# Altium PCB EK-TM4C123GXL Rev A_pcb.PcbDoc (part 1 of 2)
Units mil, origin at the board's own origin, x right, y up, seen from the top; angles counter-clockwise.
Board outline 2000 x 2600 mil, 2 copper layers (Top, Bottom), stack 12.7 mil thick; 107 components, 90 nets, 409 pads, 197 vias.
Unrouted connection lines stored in the file: 66.
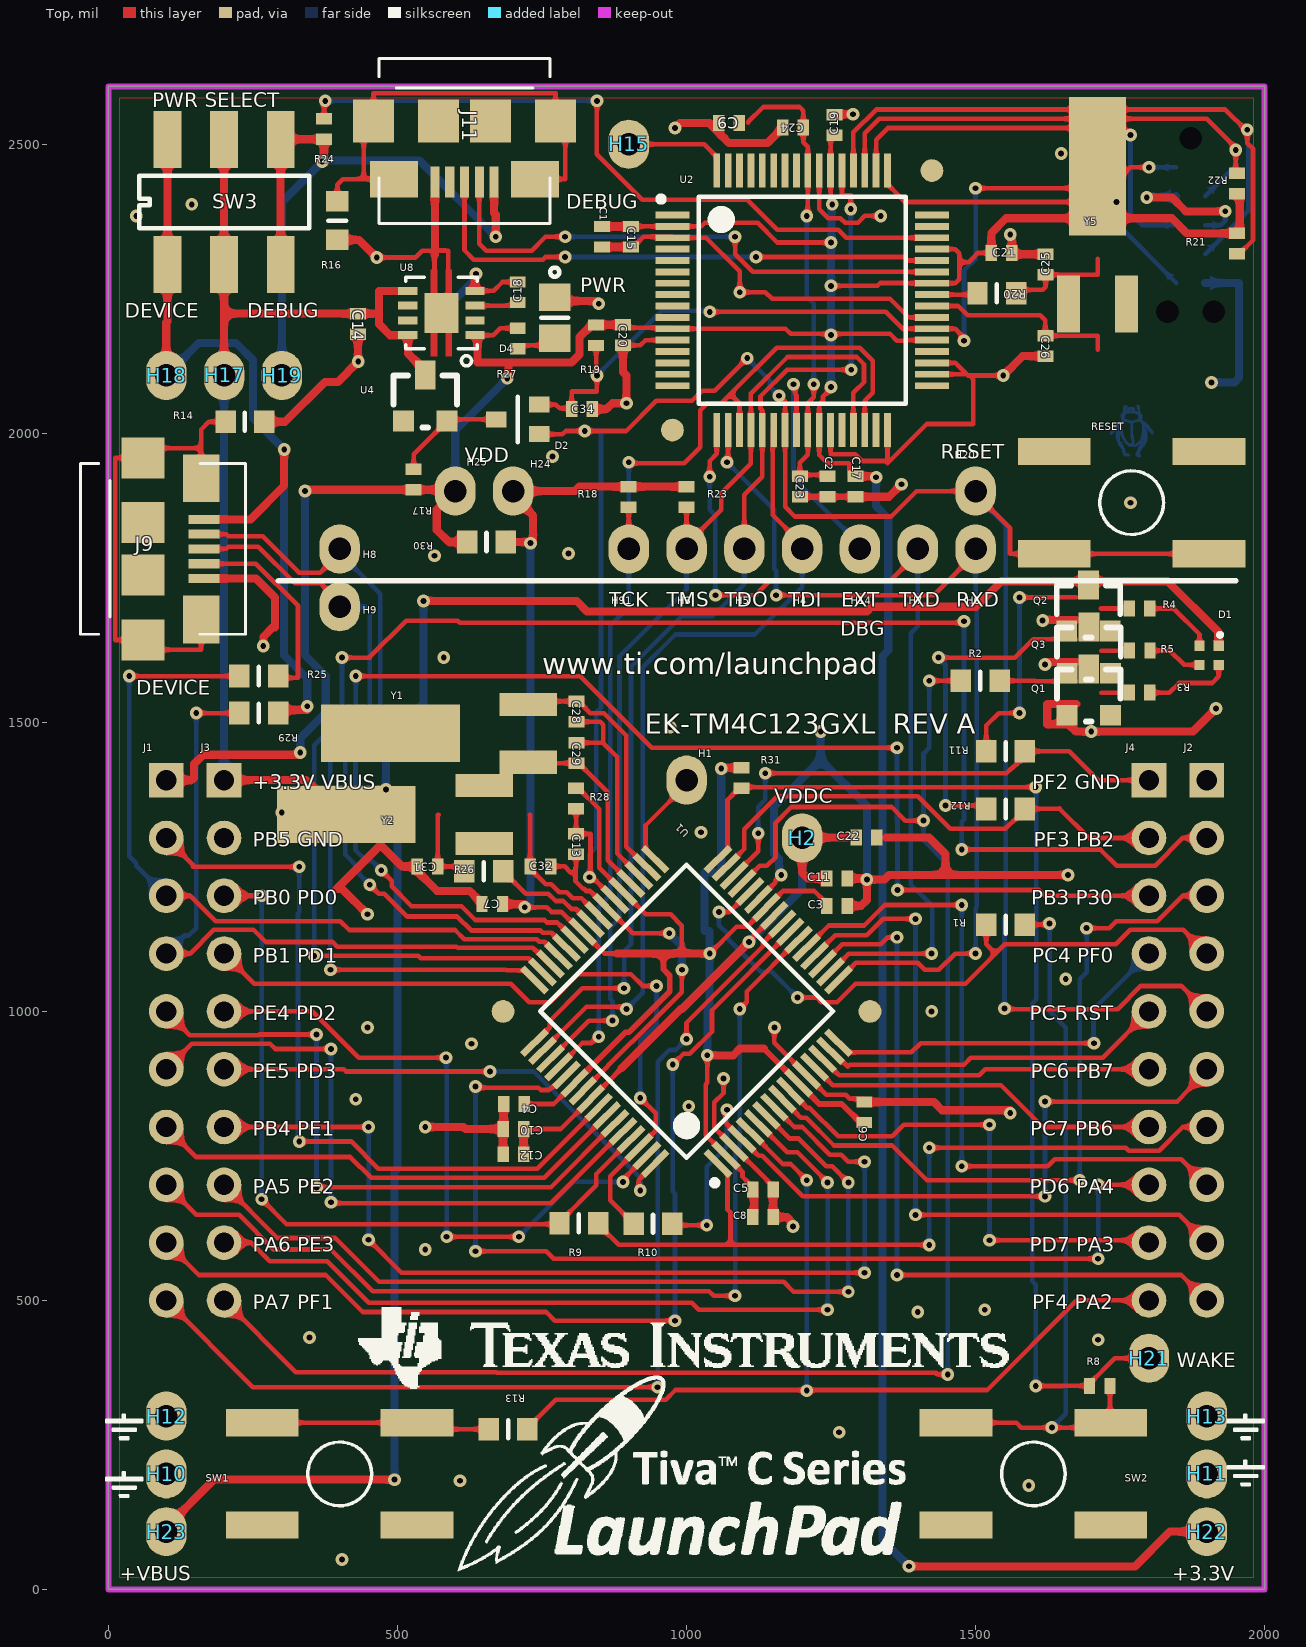
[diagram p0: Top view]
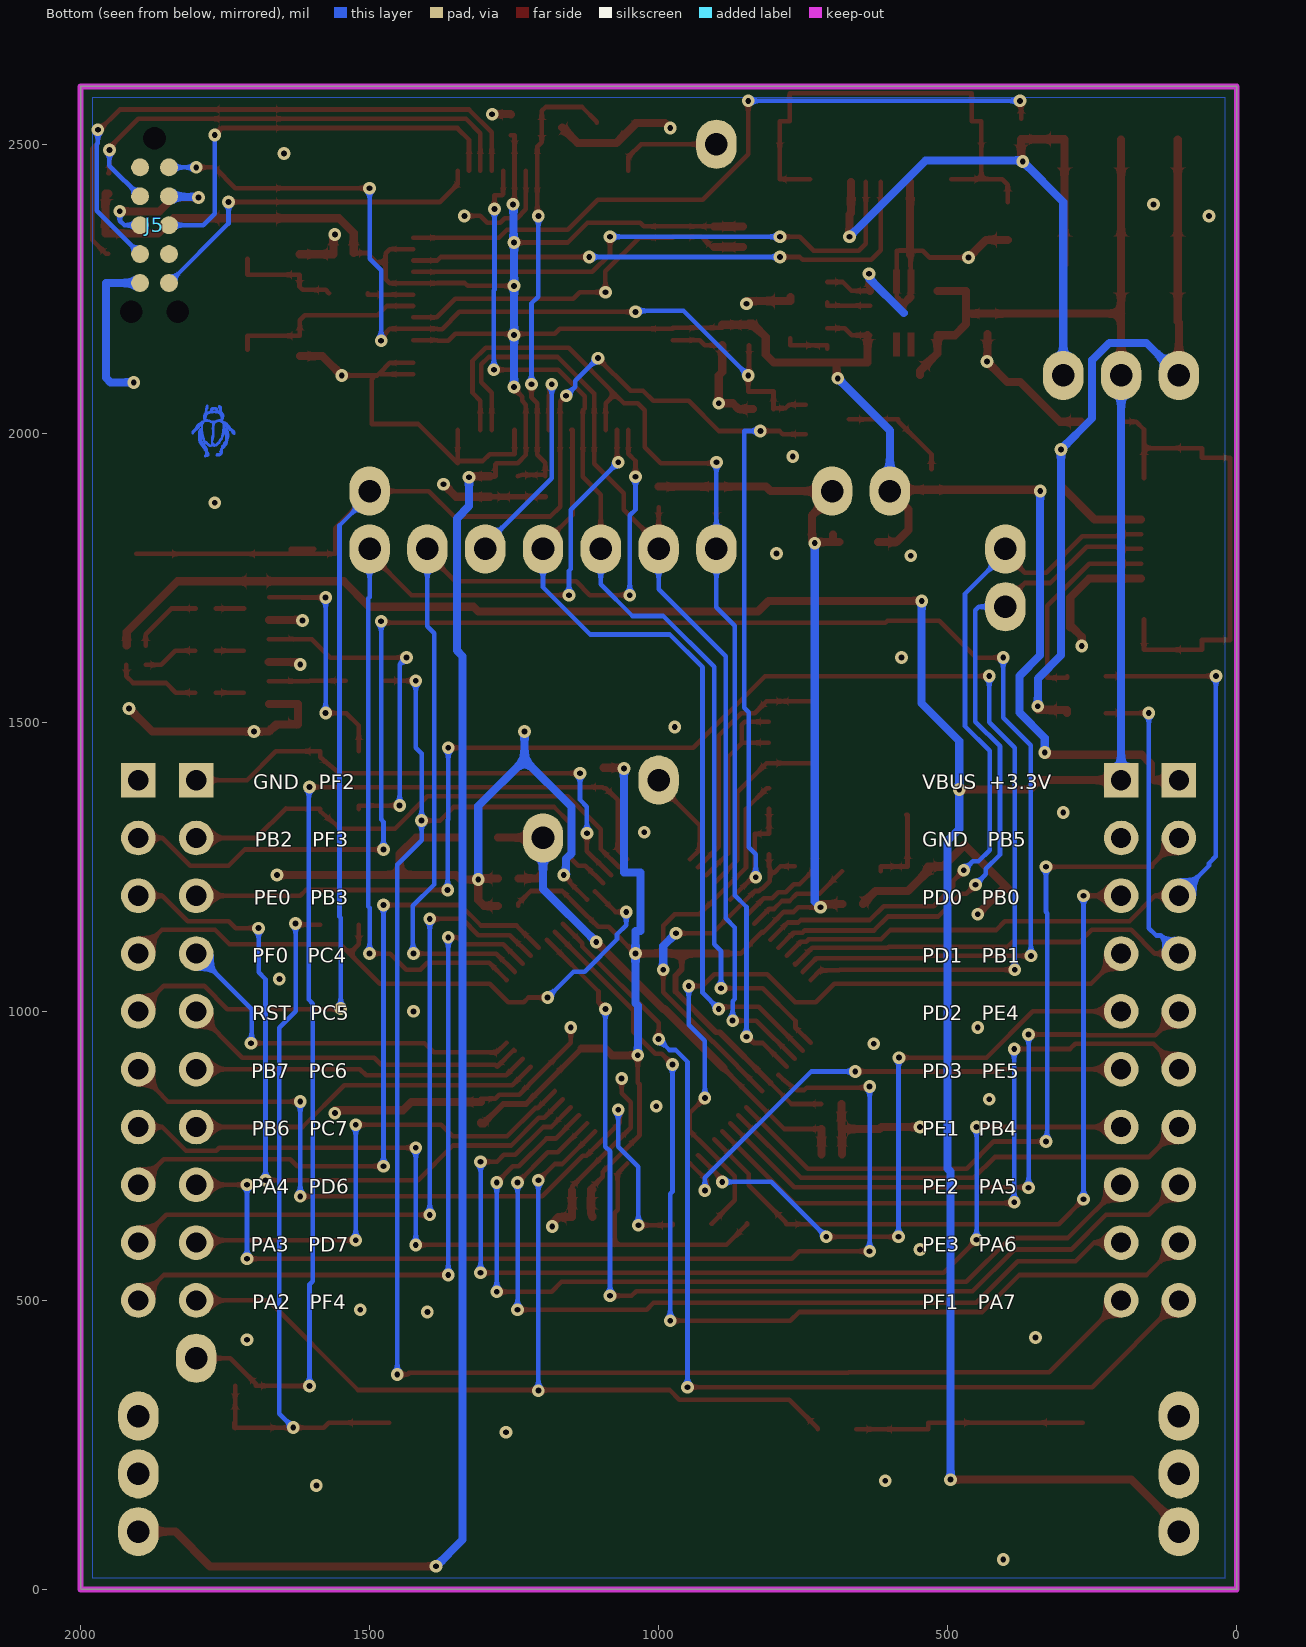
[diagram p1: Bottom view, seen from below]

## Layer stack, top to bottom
Solder Mask Top: solder mask 0.4, Solder Resist, Dk 3.5
Top: signal copper 1.35
Dielectric 1: dielectric 10, FR-4, Dk 4.3
Bottom: signal copper 1.35
Solder Mask Bottom: solder mask 0.4, Solder Resist, Dk 3.5

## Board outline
0,0 0,2600 2000,2600 2000,0

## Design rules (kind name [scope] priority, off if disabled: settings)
Clearance "Clearance - Default - DEFAULT - Via" [IsVia vs IsVia] p1: gap=7
Clearance "Clearance - Default - DEFAULT- SMD" [IsVia vs IsSMTPin] p2: gap=7
Clearance "Clearance - Default - DEFAULT - Net" [All] p3: gap=7 except(10: Text-Text)
ComponentClearance "ComponentClearance - Default - DEFAULT" [All] p1: gap=10 collisioncheckmode=3 verticalgap=10 showdistances=FALSE
DiffPairsRouting "DiffPairsRouting - DiffPair - USB_D" [InDifferentialPair('USB_D')] p1: maxlimit=10 minlimit=10 mostfreqgap=10 toplayer_minwidth=8 toplayer_maxwidth=8 toplayer_prefwidth=8 bottomlayer_minwidth=8 bottomlayer_maxwidth=8 bottomlayer_prefwidth=8 maxuncoupledlength=500
FanoutControl Fanout_SOIC [IsSOIC] p1: bgadir=Out bgaviamode=Centered fanoutstyle=Auto fanoutdirection=Alternating viagrid=1 // Fanout_SOIC (Default Rule)
FanoutControl Fanout_Small [(CompPinCount < 5)] p2: bgadir=Out bgaviamode=Centered fanoutstyle=Auto fanoutdirection=OutThenIn viagrid=1 // Fanout_Small (Default Rule)
FanoutControl Fanout_LCC [IsLCC] p3: bgadir=Out bgaviamode=Centered fanoutstyle=Auto fanoutdirection=Alternating viagrid=1 // Fanout_LCC (Default Rule)
FanoutControl Fanout_BGA [IsBGA] p4: bgadir=Out bgaviamode=Centered fanoutstyle=Auto fanoutdirection=Alternating viagrid=1 // Fanout_BGA (Default Rule)
HoleToHoleClearance "HoleToHoleClearance - Default - DEFAULT" [All] p1: gap=10 allowstackedmicrovias=TRUE
Length "Length - DiffPair - USB_D" [InDifferentialPair('USB_D')] p1: maxlimit=50000 minlimit=0
Length "Default Length" [All] p2: maxlimit=50000 minlimit=0
MatchedLengths "MatchedLengths - DiffPair - USB_D" [InDifferentialPair('USB_D')] p1: tolerance=200 checknetsindiffpair=TRUE checkdiffpairvsdiffpair=FALSE checkxsignals=FALSE checkothers=FALSE
MaxMinImpedance "Default Impedance" [All] p1: minimum=50,00 maximum=150,0
ParallelSegment "Default Parallel Segment Same Layer" [All] p1: limit=1000 gap=200
ParallelSegment "Default Parallel Segment Adjasent" [All] p2: limit=1000 gap=200
PlaneConnect "Default PlaneConnect" [All] p1: planeconnectstyle=Relief reliefexpansion=20 reliefentries=0 reliefconductorwidth=10 reliefairgap=10
PolygonConnect "PolygonConnect - Default SMT" [IsSMTPin] p1: connectstyle=Relief reliefconductorwidth=10 reliefentries=4 polygonreliefangle="45 Angle" airgapwidth=10
PolygonConnect "PolygonConnect - Default Pad" [All] p2: connectstyle=Relief reliefconductorwidth=10 reliefentries=4 polygonreliefangle="45 Angle" airgapwidth=10
RoutingLayers "RoutingLayers - Default - DEFAULT" [All] p1: top layer_v5=TRUE bottom layer_v5=TRUE
RoutingPriority "RoutingPriority - Default - DEFAULT" [All] p1: routingpriority=3
RoutingTopology "Default Routing Topology" [All] p1: topology=Shortest
RoutingVias "RoutingVias - Default - DEFAULT" [All] p1: holewidth=10 width=22 viastyle="Through Hole" minholewidth=10 minwidth=22 maxholewidth=10 maxwidth=22
SMDToCorner "SMDToCorner - Default - DEFAULT" [All] p1: distance=70000
SolderMaskExpansion "SolderMaskExpansion from CAM settings" [All] p1: expansion=5
Width "Width - NetClass - CLASS_0" [InNetClass('CLASS_0')] p1: maxlimit=14 minlimit=8 preferedwidth=14
Width "Default Width" [All] p2: maxlimit=8 minlimit=8 preferedwidth=8
19 further rules are at their usual default settings.

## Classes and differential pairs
net class CLASS_0: +3.3V +ICDI_VBUS +MCU_PWR +MCU_VDDC +USB_VBUS +VBUS GND
differential pair USB_D: +USB_DP -USB_DM

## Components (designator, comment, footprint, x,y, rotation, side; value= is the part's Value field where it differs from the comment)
C1 "CAPC0402N" CAPC0402N 853.75,2340.02 r270 top
C2 "CAPC0402N" CAPC0402N 1244,1908 r270 top
C3 "CAPC0402N" CAPC0402N 1260.48,1182.63 r0 top
C4 "CAPC0402N" CAPC0402N 701.43,839.77 r180 top
C5 "CAPC0402N" CAPC0402N 1132,692 r0 top
C6 "CAPC0402N" CAPC0402N 1307.38,825.52 r90 top
C7 "CAPC0402N" CAPC0402N 663.91,1185.82 r180 top
C8 "CAPC0402N" CAPC0402N 1132,644 r0 top
C9 "CAPC0402N" CAPC0402N 1073.59,2537.02 r180 top
C10 "CAPC0402N" CAPC0402N 700.95,796.54 r180 top
C11 "CAPC0402N" CAPC0402N 1260,1230 r0 top
C12 "CAPC0402N" CAPC0402N 700.48,752.84 r180 top
C13 "CAPC0402N" CAPC0402N 808.97,1289.39 r270 top
C14 "CAPC0402N" CAPC0402N 431.44,2189.32 r270 top
C15 "CAPC0402N" CAPC0402N 904,2340 r270 top
C17 "CAPC0402N" CAPC0402N 1292,1908 r270 top
C18 "CAPC0402N" CAPC0402N 708,2244 r90 top
C19 "CAPC0402N" CAPC0402N 1255.65,2533.39 r90 top
C20 "CAPC0402N" CAPC0402N 890,2170 r270 top
C21 "CAPC0402N" CAPC0402N 1545.01,2311.96 r0 top
C22 "CAPC0402N" CAPC0402N 1311.41,1300.63 r0 top
C23 "CAPC0402N" CAPC0402N 1196,1908 r270 top
C24 "CAPC0402N" CAPC0402N 1184.34,2528.94 r180 top
C25 "CAPC0402N" CAPC0402N 1621.26,2291.93 r90 top
C26 "CAPC0402N" CAPC0402N 1620.61,2151.07 r270 top
C28 "CAPC0402N" CAPC0402N 809.45,1518.67 r270 top
C29 "CAPC0402N" CAPC0402N 809.45,1447.07 r270 top
C31 "CAPC0402N" CAPC0402N 551.81,1250.59 r180 top
C32 "CAPC0402N" CAPC0402N 747.1,1250.85 r0 top
C34 "CAPC0402N" CAPC0402N 819.03,2041.82 r0 top
D1 "0404_QUAD" 0404_QUAD 1904,1616 r270 top
D2 "SC70-3" SC70-3 708,2024 r180 top
D4 "DIOC0805N" DIOC0805N 772,2200 r270 top
H1 "PAD70H39" PAD70H39 1000,1400 r0 top
H2 "PAD70H39" PAD70H39 1200,1300 r0 top
H3 "PAD70H39" PAD70H39 1000,1800 r0 top
H4 "PAD70H39" PAD70H39 1200,1800 r0 top
H5 "PAD70H39" PAD70H39 1100,1800 r0 top
H6 "PAD70H39" PAD70H39 1500,1800 r0 top
H7 "PAD70H39" PAD70H39 1400,1800 r0 top
H8 "PAD70H39" PAD70H39 400,1800 r0 top
H9 "PAD70H39" PAD70H39 400,1700 r0 top
H10 "PAD70H39" PAD70H39 100,200 r0 top
H11 "PAD70H39" PAD70H39 1900,200 r0 top
H12 "PAD70H39" PAD70H39 100,300 r0 top
H13 "PAD70H39" PAD70H39 1900,300 r0 top
H14 "PAD70H39" PAD70H39 1300,1800 r0 top
H15 "PAD70H39" PAD70H39 900,2500 r0 top
H17 "PAD70H39" PAD70H39 200,2100 r0 top
H18 "PAD70H39" PAD70H39 100,2100 r0 top
H19 "PAD70H39" PAD70H39 300,2100 r0 top
H20 "PAD70H39" PAD70H39 1500,1900 r0 top
H21 "PAD70H39" PAD70H39 1800,400 r0 top
H22 "PAD70H39" PAD70H39 1900,100 r0 top
H23 "PAD70H39" PAD70H39 100,100 r0 top
H24 "PAD70H39" PAD70H39 700,1900 r0 top
H25 "PAD70H39" PAD70H39 600,1900 r0 top
H91 "PAD70H39" PAD70H39 900,1800 r0 top
J1 "TSW-110-100" TSW-110-100 100,1400 r0 top
J2 "TSW-110-100" TSW-110-100 1900,1400 r0 top
J3 "TSW-110-100" TSW-110-100 200,1400 r0 top
J4 "TSW-110-100" TSW-110-100 1800,1400 r0 top
J5 "TC2050-IDC-NL" TC2050-IDC-NL 1872,2360 r270 bottom
J9 "CON-USB-MICRO-S" CON-USB-MICRO-S 60,1800 r0 top
J11 "CON-USB-MICRO-S" CON-USB-MICRO-S 616,2540 r270 top
Q1 "SOT23" SOT23 1695.78,1551.33 r0 top
Q2 "SOT23" SOT23 1695.38,1696.82 r0 top
Q3 "SOT23" SOT23 1696,1624 r0 top
R1 "RESC0603N" RESC0603N 1552,1150 r0 top
R2 "RESC0603N" RESC0603N 1508,1572 r0 top
R3 "RESC0402N" RESC0402N 1783.78,1551.33 r0 top
R4 "RESC0402N" RESC0402N 1783.38,1696.82 r0 top
R5 "RESC0402N" RESC0402N 1784,1624 r0 top
R8 "RESC0402N" RESC0402N 1714.79,352.28 r0 top
R9 "RESC0603N" RESC0603N 813.73,633.34 r0 top
R10 "RESC0603N" RESC0603N 942.02,632.6 r0 top
R11 "RESC0603N" RESC0603N 1552,1450 r180 top
R12 "RESC0603N" RESC0603N 1552,1350 r180 top
R13 "RESC0603N" RESC0603N 691.28,277.06 r180 top
R14 "RESC0603N" RESC0603N 236,2020 r0 top
R16 "RESC0603N" RESC0603N 396,2368 r270 top
R17 "RESC0402N" RESC0402N 528,1920 r90 top
R18 "RESC0402N" RESC0402N 900,1890 r270 top
R19 "RESC0402N" RESC0402N 843.63,2169.67 r270 top
R20 "RESC0603N" RESC0603N 1536.82,2242.17 r180 top
R21 "RESC0402N" RESC0402N 1952,2328 r270 top
R22 "RESC0402N" RESC0402N 1952,2432 r90 top
R23 "RESC0402N" RESC0402N 1000,1890 r270 top
R24 "RESC0402N" RESC0402N 372.94,2526.34 r270 top
R25 "RESC0603N" RESC0603N 260,1580 r0 top
R26 "RESC0603N" RESC0603N 649.32,1242.46 r0 top
R27 "RESC0402N" RESC0402N 708,2164 r270 top
R28 "RESC0402N" RESC0402N 808.97,1368.29 r270 top
R29 "RESC0603N" RESC0603N 260,1516 r180 top
R30 "RESC0603N" RESC0603N 654,1812 r180 top
R31 "RESC0402N" RESC0402N 1095.16,1403.7 r270 top
RESET "SW-EVQQ2" SW-EVQQ2 1770,1880 r0 top
SW1 "SW-EVQQ2" SW-EVQQ2 400,200 r0 top
SW2 "SW-EVQQ2" SW-EVQQ2 1600,200 r0 top
SW3 "SW_JS202011SCQN" SW_JS202011SCQN 200,2400 r90 top
U1 "QFP50P1200X1200X160-64N" QFP50P1200X1200X160-64N 1000,1000 r135 top
U2 "QFP50P1200X1200X160-64N" QFP50P1200X1200X160-64N 1200,2230 r0 top
U4 "SOT23" SOT23 548,2060 r0 top
U8 "TI-DRB-SON8" TI-DRB-SON8 576,2208 r90 top
Y1 "XTAL-AB26TRA" XTAL-AB26TRA 726.3,1480.94 r0 top
Y2 "XTAL-AB26TRA" XTAL-AB26TRA 650.08,1340.44 r0 top
Y5 "XTAL-AB26TRA" XTAL-AB26TRA 1711.07,2223.44 r270 top

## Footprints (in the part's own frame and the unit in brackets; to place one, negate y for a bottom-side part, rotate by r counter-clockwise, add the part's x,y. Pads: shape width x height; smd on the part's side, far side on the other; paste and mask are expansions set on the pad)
0404_QUAD [mm]
  rrect0% 0.45x0.45 smd: 1(-0.423,0.423) 2(0.423,0.423) 3(0.423,-0.423) 4(-0.423,-0.423)
  silkscreen extent -0.98,0.41 -0.82,0.56
CAPC0402N [mm]
  rect 0.5x0.7 smd: 1(-0.45,0) 2(0.45,0)
CON-USB-MICRO-S [mm]
  rect 1.35x0.4 smd: 1(2.675,1.3) 2(2.675,0.65) 3(2.675,0) 4(2.675,-0.65) 5(2.675,-1.3)
  rect 1.6x2.1 smd: 6(2.55,3.1) 7(2.55,-3.1)
  rect 1.9x1.8 smd: 8(0,4) 9(0,-4) 10(0,1.15) 11(0,-1.15)
  silkscreen extent -2.75,-3.75 4.5,3.75
DIOC0805N [mm]
  rect 1.2x1.4 smd: 1(-0.9,0) 2(0.9,0)
  silkscreen extent -2.2,-0.6 0,0.6
PAD70H39 [mil]
  oval 70x85 / inner round 70 / far side oval 70x85 hole 39: 1(0,0)
QFP50P1200X1200X160-64N [mm]
  rect 1.5x0.3 smd: 1(-5.7,3.75) 2(-5.7,3.25) 3(-5.7,2.75) 4(-5.7,2.25) 5(-5.7,1.75) 6(-5.7,1.25) 7(-5.7,0.75) 8(-5.7,0.25) 9(-5.7,-0.25) 10(-5.7,-0.75) 11(-5.7,-1.25) 12(-5.7,-1.75) 13(-5.7,-2.25) 14(-5.7,-2.75) 15(-5.7,-3.25) 16(-5.7,-3.75) 33(5.7,-3.75) 34(5.7,-3.25) 35(5.7,-2.75) 36(5.7,-2.25) 37(5.7,-1.75) 38(5.7,-1.25) 39(5.7,-0.75) 40(5.7,-0.25) 41(5.7,0.25) 42(5.7,0.75) 43(5.7,1.25) 44(5.7,1.75) 45(5.7,2.25) 46(5.7,2.75) 47(5.7,3.25) 48(5.7,3.75)
  rect 0.3x1.5 smd: 17(-3.75,-5.7) 18(-3.25,-5.7) 19(-2.75,-5.7) 20(-2.25,-5.7) 21(-1.75,-5.7) 22(-1.25,-5.7) 23(-0.75,-5.7) 24(-0.25,-5.7) 25(0.25,-5.7) 26(0.75,-5.7) 27(1.25,-5.7) 28(1.75,-5.7) 29(2.25,-5.7) 30(2.75,-5.7) 31(3.25,-5.7) 32(3.75,-5.7) 49(3.75,5.7) 50(3.25,5.7) 51(2.75,5.7) 52(2.25,5.7) 53(1.75,5.7) 54(1.25,5.7) 55(0.75,5.7) 56(0.25,5.7) 57(-0.25,5.7) 58(-0.75,5.7) 59(-1.25,5.7) 60(-1.75,5.7) 61(-2.25,5.7) 62(-2.75,5.7) 63(-3.25,5.7) 64(-3.75,5.7)
  round 1 smd mask+0.5: 65(-5.7,-5.7) 66(5.7,5.7)
  Top pour cut-out: 6.7,5.7 6.624,6.083 6.407,6.407 6.083,6.624 5.7,6.7 5.7,6.7 5.317,6.624 4.993,6.407 4.776,6.083 4.7,5.7 4.7,5.7 4.776,5.317 4.993,4.993 5.317,4.776 5.7,4.7 5.7,4.7 6.083,4.776 6.407,4.993 6.624,5.317 6.7,5.7
  Top pour cut-out: -4.7,-5.7 -4.776,-5.317 -4.993,-4.993 -5.317,-4.776 -5.7,-4.7 -5.7,-4.7 -6.083,-4.776 -6.407,-4.993 -6.624,-5.317 -6.7,-5.7 -6.7,-5.7 -6.624,-6.083 -6.407,-6.407 -6.083,-6.624 -5.7,-6.7 -5.7,-6.7 -5.317,-6.624 -4.993,-6.407 -4.776,-6.083 -4.7,-5.7
  silkscreen extent -6.32,-4.55 4.55,4.57
RESC0402N [mm]
  rect 0.5x0.7 smd: 1(-0.45,0) 2(0.45,0)
RESC0603N [mm]
  rect 0.9x1 smd: 1(-0.85,0) 2(0.85,0)
  silkscreen extent 0,-0.4 0,0.4
SC70-3 [mm]
  rect 0.9x0.7 smd: 1(-0.95,0.65) 2(-0.95,-0.65) 3(0.95,0)
  silkscreen extent 0,-1 0,1
SOT23 [mil]
  rect 36x36 smd: 1(-37.5,-39) 2(37.5,-39)
  rect 36x50 smd: 3(0,41)
  silkscreen extent -55,-50 55,40
SW-EVQQ2 [mm]
  rect 3.2x1.2 smd: 1(-3.4,2.25) 2(-3.4,-2.25) 3(3.4,2.25) 4(3.4,-2.25)
  silkscreen extent -1.4,-1.4 1.4,1.4
SW_JS202011SCQN [mil]
  rect 98.5x48 smd: 1(-108.25,98) 2(-108.25,0) 3(-108.25,-98) 4(108.25,-98) 5(108.25,0) 6(108.25,98)
  silkscreen extent -45,-147 45,147
TC2050-IDC-NL [mil]
  round 31 smd paste-15.5: 1(-100,-25) 2(-50,-25) 3(0,-25) 4(50,-25) 5(100,-25) 6(100,25) 7(50,25) 8(0,25) 9(-50,25) 10(-100,25)
  round 0 hole 39 unplated: 11(-150,0) 12(150,-40) 13(150,40)
  Top pour cut-out: -100,-14 100,-14 100,13 -100,13 -100,-14
TI-DRB-SON8 [mm]
  rect 0.35x0.85 smd: 1(-0.975,-1.475) 2(-0.325,-1.475) 3(0.325,-1.475) 4(0.975,-1.475) 5(0.975,1.475) 6(0.325,1.475) 7(-0.325,1.475) 8(-0.975,1.475)
  rrect1% 1.75x1.5 smd paste-0.1: 9(0,0)
  round 0 all layers, no hole: 10(0,0) 11(0,0) 12(0,0) 13(0,0)
  Top region: 1.9,-0.185 0.875,-0.185 0.875,-0.465 1.9,-0.465 1.9,-0.185
  Top region: 1.9,0.465 0.875,0.465 0.875,0.185 1.9,0.185 1.9,0.465
  Top region: -0.875,-0.185 -1.9,-0.185 -1.9,-0.465 -0.875,-0.465 -0.875,-0.185
  Top region: -0.875,0.465 -1.9,0.465 -1.9,0.185 -0.875,0.185 -0.875,0.465
  silkscreen extent -2.32,-1.58 1.58,1.58
TSW-110-100 [mil]
  rect 60x60 / inner round 60 / far side rect 60x60 hole 35: 1(0,0)
  round 60 hole 35: 2(0,-100) 3(0,-200) 4(0,-300) 5(0,-400) 6(0,-500) 7(0,-600) 8(0,-700) 9(0,-800) 10(0,-900)
XTAL-AB26TRA [mil]
  rect 99x40 smd: 1(0,-50) 2(0,50)
  rect 240x99 smd: 3(-238.5,0)

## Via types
v1: diameter 22, hole 10, Top to Bottom, 197 vias

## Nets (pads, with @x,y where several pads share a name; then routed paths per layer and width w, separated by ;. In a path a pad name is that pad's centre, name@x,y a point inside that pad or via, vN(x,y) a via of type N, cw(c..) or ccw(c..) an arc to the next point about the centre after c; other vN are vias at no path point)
$$$7473: R4.1 | length 48.6
  Top w8: 1717.04,1696.82 1734.75,1696.82 R4.1@1765.66,1696.82
$$$7634: C29.2 U1.36 Y1.1 | length 334.2
  Top w8: Y1.1@726.3,1430.94 726.3,1429.35 813.39,1429.35 864,1378.74 864,1261.27 U1.36@903.96,1221.32
$$$7643: C28.2 C29.1 U1.35 | length 381.9
  Top w8: C29.1@809.45,1464.79 855.21,1464.79 856,1464 ; C28.2@809.45,1500.95 851.05,1500.95 856,1496 856,1464 ; U1.35@917.88,1235.24 880,1273.11 880,1440 856,1464
$$$7651: C28.1 U1.34 Y1.2 | length 442.5
  Top w8: Y1.2@726.3,1530.94 726.3,1536.39 C28.1@809.45,1536.39 813.39,1536.39 833.77,1516 857.21,1516 896,1477.21 896,1284.95 U1.34@931.79,1249.16
$$$9519: D4.2 R27.2 | length 82.3
  Top w8: R27.2@708,2146.28 708,2152.13 772,2152.13 D4.2@772,2164.57
$$$9631: C2.1 C9.1 C23.1 C24.1 U2.25 U2.56 | length 810.8
  Top w8: 1107.05,2537.02 1107.05,2538.98 1132.54,2564.48 1195.52,2564.48 1202.06,2557.94 1202.06,2503.78 1209.84,2496 U2.56@1209.84,2454.41 1209.84,2376 v1(1208,2376) ; C23.1@1196,1925.72 C23.1@1196,1928 ; v1(1220,2085) 1220,2062.11 1209.84,2051.95 U2.25@1209.84,2005.59 1209.84,1962.73 1196,1948.89 C23.1@1196,1928 ; C2.1@1244,1925.72 1236,1928 C23.1@1196,1928
  Bottom w8: v1(1208,2376) 1208,2236.5 1220,2224.5 v1(1220,2085)
$$$9798: J11.2 U2.43 | length 947.2
  Top w8: J11.2@641.59,2434.68 641.59,2328 653.59,2316 732,2316 756,2340 v1(790,2340) ; v1(1084,2340) 1084,2309.89 1114.67,2279.21 U2.43@1424.41,2279.21
  Bottom w8: v1(790,2340) v1(1084,2340)
$$$9803: J11.3 U2.44 | length 937.9
  Top w8: J11.3@616,2434.68 616,2316.33 632,2300.33 751,2300.33 751.5,2300.83 751.84,2300.83 756.01,2305 v1(790,2305) ; v1(1120,2305) 1376.78,2305 1382.88,2298.9 U2.44@1424.41,2298.9
  Bottom w8: v1(790,2305) v1(1120,2305)
$$$9866: R24.1 U2.46 | length 1236.9
  Top w8: R24.1@372.94,2544.06 372.94,2572.94 v1(375,2575) v1@376,2576 ; v1(845,2575) 845,2482.45 923.45,2404 1105.06,2404 1157.06,2352 1262.32,2352 1276.06,2338.27 U2.46@1424.41,2338.27
  Bottom w8: v1(375,2575) v1(845,2575) v1@847,2575
$$$9915: J11.6 J11.7 J11.8 J11.9 R16.1 | length 831.1
  Top w8: R16.1@396,2399.61 R16.1@396,2401.46 396,2430.18 405.43,2439.61 441.61,2439.61 ; J11.7@493.95,2439.61 441.61,2439.61 ; J11.6@738.05,2439.61 790.39,2439.61 790.39,2540 J11.8@773.48,2540 773.48,2588.4 458.52,2588.4 J11.9@458.52,2540 441.61,2540 441.61,2439.61
$$$10194: H15.1 U2.64 | length 185.1
  Top w8: H15.1@900,2500 1030.39,2500 1052.36,2478.03 U2.64@1052.36,2454.41
$$$10897: J9.6 J9.7 J9.8 J9.9 R14.1 | length 830.9
  Top w8: J9.7@160.39,1677.95 160.39,1625.61 60,1625.61 J9.9@60,1642.52 11.6,1642.52 11.6,1957.48 J9.8@60,1957.48 60,1974.39 160.39,1974.39 ; J9.6@160.39,1922.05 160.39,1974.39 ; R14.1@202.54,2020 200.39,2020 173.82,2020 160.39,2006.57 160.39,1974.39
$$$11787: R5.1 | length 48.6
  Top w8: 1717.65,1624 R5.1@1766.28,1624
$$$11789: R3.1 | length 48.6
  Top w8: 1717.43,1551.33 1735.15,1551.33 R3.1@1766.06,1551.33
$$$18869: D2.3 R17.2 U4.2 | length 195.2
  Top w8: R17.2@528,1937.72 528,1963.5 U4.2@585.5,2021 585.5,2024 D2.3@670.6,2024
$$$29924: J9.4 R25.2 | length 354.9
  Top w8: J9.4@165.32,1774.41 255.05,1774.41 328,1701.46 328,1577 293.46,1577 R25.2@293.46,1580
$$$30695: C32.1 U1.40 Y2.2 | length 246.6
  Top w8: 728.82,1340.44 729.39,1340.44 C32.1@729.39,1250.85 729.39,1246.91 756.26,1220.04 766.08,1220.04 780.13,1205.98 792.8,1205.98 803.24,1195.55 818.37,1195.55 U1.40@848.28,1165.64
$$$30696: C31.1 R26.1 Y2.1 | length 146.1
  Top w8: 571.34,1340.44 569.52,1340.44 C31.1@569.52,1250.59 615.86,1250.59 R26.1@615.86,1242.46
$$$30742: R20.2 U2.41 | length 81.3
  Top w8: U2.41@1424.41,2239.84 1503.35,2239.84 R20.2@1503.35,2242.17
$$$30799: R26.2 U1.41 | length 189.2
  Top w8: R26.2@682.79,1242.46 721.73,1203.52 761.06,1203.52 773.62,1190.96 786.61,1190.96 800.37,1177.2 808.88,1177.2 U1.41@834.36,1151.72
$$$31114: D1.2 R3.2 | length 150.7
  Top w8: R3.2@1801.5,1551.33 1835.33,1551.33 1852,1568 1909.13,1568 1920.63,1579.51 D1.2@1920.63,1599.37
$$$31119: D1.3 R5.2 | length 95.9
  Top w8: R5.2@1801.72,1624 1836,1624 1860.63,1599.37 D1.3@1887.37,1599.37
$$$31122: D1.4 R4.2 | length 124.5
  Top w8: R4.2@1801.1,1696.82 1843.04,1696.82 1887.37,1652.49 D1.4@1887.37,1632.63
$$$31216: C18.1 U8.3 | length 79.4
  Top w8: U8.3@634.07,2220.8 708,2220.8 C18.1@708,2226.28
$$$32514: C25.1 R20.1 Y5.1 | length 194.3
  Top w8: R20.1@1570.28,2242.17 1570.28,2242.28 1576,2248 1615.89,2248 1621.26,2253.37 C25.1@1621.26,2274.22 1711.07,2274.22 1711.07,2302.18
$$$32515: C26.1 U2.40 Y5.2 | length 347.6
  Top w8: U2.40@1424.41,2220.16 1470.2,2220.16 1486.36,2204 1612,2204 1620.61,2195.39 C26.1@1620.61,2168.79 1711.07,2168.79 1711.07,2144.7
+3.3V: C1.1 C15.1 C17.1 C19.1 C20.1 C21.1 H22.1 H25.1 J1.1 R17.1 R19.1 R21.1 R22.1 R27.1 R30.2 U2.2 U2.11 U2.26 U2.37 U2.42 U2.45 U2.54 U8.1 | length 6912.6
  Top w8: U8.1@634.07,2169.61 638.44,2169.61 665.61,2169.61 677.72,2181.72 R27.1@708,2181.72 ; C20.1@890,2187.72 890,2182.49 975.59,2182.49 U2.11@975.59,2180.79 1171.21,2180.79 1180,2172 v1@1248,2172 ; C15.1@904,2357.72 904,2357.95 U2.2@975.59,2357.95 1025.95,2357.95 1032,2364 1123.06,2364 1157.06,2330 v1(1250,2330) ; v1(1250,2080) 1251.56,2078.44 1236,2062.89 1236,2056 1229.53,2049.53 U2.26@1229.53,2005.59 1229.53,1962.47 1244,1948 1280.78,1948 1282.22,1946.56 1282.22,1925.72 C17.1@1292,1925.72 ; v1(1250,2170) v1@1248,2172 ; v1(1250,2255) 1330.29,2255 1335.29,2260 1382.41,2260 1382.88,2259.53 U2.42@1424.41,2259.53 1464.94,2259.53 1472,2266.59 1472,2296 ; v1(1252,2396) 1249.21,2396 U2.54@1249.21,2454.41 1249.21,2515.68 C19.1@1255.65,2515.68 ; U2.37@1424.41,2161.1 1382.88,2161.1 1381.78,2160 1364,2160 1352,2172 v1@1248,2172 ; U2.45@1424.41,2318.58 1464.94,2318.58 1472,2311.52 1472,2296 ; 1496,2304 1488,2296 1472,2296 ; 1496.04,2304 1504,2311.96 C21.1@1527.3,2311.96
  Top w14: J1.1@100,1400 144,1400 148,1404 148,1427.8 164.2,1444 332,1444 v1(332,1448) ; v1(340,1900) 342.28,1902.28 R17.1@528,1902.28 600,1902.28 H25.1@600,1900 568,1868 568,1832.82 588.82,1812 R30.2@620.54,1812 ; U8.1@638.44,2169.61 638.44,2122.44 688.42,2122.44 ; v1(690,2095) 691,2095 692,2096 692,2118.86 688.42,2122.44 ; R19.1@843.63,2187.38 R19.1@843.63,2187.72 ; C1.1@853.75,2357.73 C15.1@904,2357.72 ; C20.1@890,2187.72 R19.1@843.63,2187.72 ; C17.1@1292,1925.72 1326.28,1925.72 v1(1328,1924) ; v1(1385,40) 1776,40 1836,100 H22.1@1900,100 ; C21.1@1527.3,2311.96 1527.3,2346.65 1552.64,2372 1839.5,2372 1865.78,2345.72 R21.1@1952,2345.72 1957,2345.72 1957,2414.28 R22.1@1952,2414.28 ; 688.42,2122.44 800.85,2122.44 814.7,2136.29 814.7,2166.45 837.67,2189.41 843.63,2189.41 R19.1@843.63,2187.72
  Bottom w14: v1(332,1448) 332,1473 376,1517 376,1580 340,1616 v1(340,1900) ; H25.1@600,1900 600,2005 v1(690,2095) ; v1(1250,2080) v1(1250,2170) v1(1250,2255) v1(1250,2330) 1251,2330 1251,2396 v1(1252,2396) ; v1(1328,1924) 1328,1873.9 1349,1852.9 1349,1624.28 1339,1614.28 1339,86 v1(1385,40)
+ICDI_VBUS: H19.1 J11.1 R24.2 SW3.3 SW3.4 | length 1192.6
  Top w14: SW3.3@298,2291.75 SW3.4@298,2508.25 298,2508.62 R24.2@372.94,2508.62 372.94,2470 v1(370,2470) ; v1@667.18,2344.82 v1@670,2342 ; J11.1@667.18,2434.68 667.18,2380.96 670,2378.15 v1@670,2342 ; v1@670,2342 672,2340 v1(670,2340) v1@670,2342
  Bottom w14: H19.1@300,2100 300,2400 v1(370,2470) 372,2472 538,2472 v1(670,2340)
+MCU_PWR: C3.1 C4.1 C5.1 C6.1 C7.1 C8.1 H24.1 R18.1 R23.1 R28.1 R30.1 R31.1 U1.2 U1.11 U1.26 U1.37 U1.42 U1.54 | length 3776.6
  Top w8: C4.1@719.14,839.77 770.17,839.77 U1.54@806.52,876.12 ; v1(720,1180) 758.41,1180 766.41,1172 783.55,1172 819.09,1136.45 U1.42@820.44,1137.8 858.24,1100 880,1100 ; R28.1@808.97,1386.01 812.9,1386.01 848.87,1350.04 848.87,1248.56 U1.37@890.04,1207.4 929.44,1168 972.46,1168 992,1148.46 992,1100 ; v1(1036,924) 1036,876.88 1033,873.88 1033,786.05 1096.86,722.18 1096.86,713.76 C5.1@1114.48,696.14 ; v1(1040,1100) 1086.45,1146.45 1104.69,1146.45 U1.26@1137.8,1179.56 1166.46,1208.22 1221.11,1208.22 1242.77,1186.56 C3.1@1242.77,1182.63 ; C5.1@1114.48,698.53 C5.1@1114.48,696.14 ; C5.1@1114.48,693.43 1114.48,692 C5.1@1114.28,692 C5.1@1114.48,693.43 ; C5.1@1114.48,693.43 C5.1@1114.48,696.14
  Top w10: U1.54@806.52,876.12 894.4,964 900.53,964 971,1034.47 971,1061.76 960,1072.76 960,1100 ; 1133.6,936 1229.6,840 1268.61,840 C6.1@1302.13,806.49
  Top w14: C7.1@681.62,1185.82 681.62,1185.52 720,1185.52 v1(720,1180) ; R30.1@687.46,1812 R30.1@698.18,1812 ; R30.1@698.18,1824.68 R30.1@698.18,1812 ; v1(730,1810) v1@732,1812 ; 880,1100 960,1100 992,1100 v1(1040,1100) ; R23.1@1000,1907.72 R18.1@900,1907.72 814.47,1907.72 806.75,1900 H24.1@700,1900 700,1892.5 734.65,1857.85 734.65,1814.65 v1@732,1812 ; v1(1036,924) 1080.8,924 1092.8,936 1133.6,936 ; v1(1060,1420) 1061.42,1421.42 R31.1@1095.16,1421.42 ; C8.1@1114.28,644 1117.13,652 1117.13,692 C5.1@1114.48,692 ; C6.1@1302.13,806.49 1307.38,806.49 C6.1@1307.38,807.8 ; R30.1@698.18,1812 v1@732,1812
  Bottom w14: v1(720,1180) 730,1190 v1(730,1810) ; v1(1036,924) 1036,1010 1040,1014 v1(1040,1100) 1040,1138.82 1031,1138.82 1031,1240 1060,1240 v1(1060,1420)
+MCU_VDDC: C10.1 C11.1 C12.1 C22.1 H2.1 U1.25 U1.56 | length 1035.1
  Top w8: C10.1@718.67,796.54 782.62,796.54 U1.56@834.36,848.28 888,901.92 ; v1(1108,1120) 1107.04,1120.96 U1.25@1151.72,1165.64
  Top w14: C12.1@718.19,752.84 718.19,796.54 C10.1@718.67,796.54 ; 888,901.92 990.08,1004 992,1004 v1(1108,1120) ; C11.1@1242.28,1230 1210,1230 1200,1240 H2.1@1200,1300 1200,1300.63 1277.94,1300.63
  Bottom w14: v1(1108,1120) 1200,1212 H2.1@1200,1300
+USB_VBUS: H18.1 J9.1 R29.1 SW3.1 SW3.6 | length 1520.5
  Top w14: H18.1@100,2100 100,2191.5 102,2193.5 SW3.1@102,2291.75 SW3.6@102,2508.25 ; J9.1@165.32,1851.18 245.89,1851.18 304,1909.29 v1(304,1972) ; R29.1@293.46,1516 293.46,1521.38 344,1521.38 v1(344,1528)
  Bottom w14: H18.1@100,2100 156.5,2156.5 220.3,2156.5 250,2126.8 250,2026 v1(304,1972) 304,1616 344,1576 v1(344,1528)
+VBUS: C14.1 D1.1 H17.1 H23.1 J3.1 SW3.2 SW3.5 U4.3 U8.5 U8.8 | length 5369
  Top w14: H23.1@100,100 100,107.5 182.5,190 v1(495,190) ; J3.1@200,1400 341.5,1400 357.5,1384 v1(480,1384) ; H17.1@200,2100 200,2207.04 ; SW3.5@200,2508.25 SW3.2@200,2291.75 200,2207.04 ; U8.5@517.93,2246.39 468,2246.39 468,2204 ; v1(545,1710) 810.05,1710 828.05,1692 1312,1692 1320,1700 1500.72,1700 1544.72,1744 1832,1744 1920,1656 1920,1632.63 D1.1@1920.63,1632.63 ; U4.3@548,2101 548,2108 517.93,2138.07 U8.8@517.93,2169.61 487.2,2169.61 468,2188.81 468,2204 ; 200,2207.04 464.96,2207.04 468,2204
  Bottom w14: J3.1@200,1400 H17.1@200,2100 ; v1(495,190) 495,723 500,728 500,1295.18 480,1315.18 v1(480,1384) 480,1468 545,1533 v1(545,1710)
\EXTDBG\: H14.1 U2.24 | length 416.1
  Top w8: v1(1185,2085) 1188.25,2085 1188.25,2068 1190.16,2066.09 U2.24@1190.16,2005.59
  Bottom w8: v1(1185,2085) 1185,1922.5 1300,1807.5 H14.1@1300,1800
\HIB: H1.1 U1.33 | length 173.2
  Top w8: U1.33@945.71,1263.08 929.01,1279.78 929.01,1321.51 1000,1392.5 H1.1@1000,1400
\TARGETRST\: C13.1 D2.1 H20.1 J2.5 R28.2 RESET.2 RESET.4 U1.38 U2.23 | length 3898.1
  Top w8: D2.1@745.4,1998.41 785.26,1998.41 790.85,2004 v1(824,2004) 895.89,2004 947.89,2056 1009.5,2056 1027.07,2073.57 1048.57,2073.57 v1(1105,2130) ; R28.2@808.97,1350.57 C13.1@808.97,1307.1 833.75,1307.1 833.87,1306.98 833.87,1235.72 v1@834.8,1234.8 ; v1(832,1232) v1@834.8,1234.8 ; U1.38@876.12,1193.48 v1@834.8,1234.8 ; v1(1160,2065) 1170.47,2054.53 U2.23@1170.47,2005.59 1170.47,1872.73 1187.2,1856 1353.78,1856 1397.78,1900 H20.1@1500,1900 1500,1895.27 1559.63,1835.63 1559.63,1791.42 RESET.2@1636.14,1791.42 ; v1(1550,1005) 1549,1005 1548,1004 1746.02,1004 1786.02,1044 1856,1044 J2.5@1900,1000 ; RESET.2@1595.39,1799.88 1636.14,1799.88 RESET.2@1636.14,1791.42 ; RESET.4@1903.86,1791.42 RESET.2@1636.14,1791.42
  Bottom w8: v1(824,2004) 852,2004 852,1525.44 844,1517.44 844,1284 832,1272 v1(832,1232) ; v1(1105,2130) 1144.44,2090.56 1144.44,2080.56 v1(1160,2065) ; H20.1@1500,1900 1500,1892.5 1552,1840.5 1552,1164 1550,1162 v1(1550,1005)
\WAKE: H21.1 R8.1 R31.2 U1.32 | length 1912.4
  Top w8: U1.32@1054.29,1263.08 1070.99,1279.78 1070.99,1365.75 1091.22,1385.98 R31.2@1095.16,1385.98 1097.17,1388 v1(1604,1388) ; v1(1604,352) 1650.98,352 1651.26,352.28 R8.1@1697.08,352.28 1697.08,356.22 1740.86,400 H21.1@1800,400
  Bottom w8: v1(1604,352) 1604,527.44 1598,533.44 1598,1013.5 1605,1020.5 1605,1388 v1(1604,1388)
DEBUG_PC0/TCK/SWCLK: H91.1 R18.2 U1.52 U2.19 U2.30 | length 1926.8
  Top w8: U1.52@778.68,903.96 819.99,945.27 835.27,945.27 846,956 v1(848,956) ; H91.1@900,1800 R18.2@900,1872.28 ; v1(900,1950) 900,1948 996,1948 1024,1976 1024,2040 1036,2052 1059.82,2052 1075.82,2068 ; U2.19@1091.73,2005.59 1091.73,2052.08 1075.82,2068 ; U2.30@1308.27,2005.59 1308.27,2056.27 1322,2070 1322,2125.33 1299.33,2148 1155.82,2148 1075.82,2068
  Bottom w8: v1(848,956) 848,1180.54 868,1200.54 868,1666.87 900,1698.87 H91.1@900,1800 v1(900,1950)
DEBUG_PC1/TMS/SWDIO: H3.1 R23.2 U1.51 U2.20 U2.29 | length 1734.9
  Top w8: U1.51@764.76,917.88 830.89,984 v1(872,984) ; H3.1@1000,1800 H3.1@1000,1807.5 ; R23.2@1000,1872.28 H3.1@1000,1807.5 ; U2.29@1288.58,2005.59 1288.58,2070.13 1307,2088.55 1307,2119.11 1294.11,2132 1174.67,2132 1111.42,2068.74 U2.20@1111.42,2005.59 1111.42,1947.42 1060,1896 1060,1867.5 H3.1@1000,1807.5
  Bottom w8: v1(872,984) 872,1017.44 868,1021.44 868,1145.09 884,1161.09 884,1614.02 1000,1730.02 H3.1@1000,1800
DEBUG_PC2/TDI: H4.1 U1.50 U2.22 | length 1430.2
  Top w8: U1.50@750.84,931.79 827.05,1008 892,1008 v1(896,1004) ; U2.22@1150.79,2005.59 1148.88,2005.59 1148.88,1858.62 1200,1807.5 H4.1@1200,1800
  Bottom w8: v1(896,1004) 924,1032 924,1595.11 980.89,1652 1118.11,1652 1200,1733.89 H4.1@1200,1800 H4.1@1200,1820.88
DEBUG_PC3/TDO/SWO: H5.1 U1.49 U2.21 U2.53 | length 1891.3
  Top w8: U1.49@736.92,945.71 763.21,972 763.21,983.32 819.89,1040 v1(892,1040) ; H5.1@1100,1800 1100,1893.73 1131.1,1924.83 U2.21@1131.1,2005.59 1131.1,2039.84 1128,2042.94 1128,2064.11 1173.89,2110 v1(1285,2110) ; U2.53@1268.9,2454.41 1268.9,2413.88 1270.78,2412 1284,2412 v1(1284,2388)
  Bottom w8: v1(892,1040) 892,1104 904,1116 904,1596.33 991.67,1684 1045.11,1684 1100,1738.89 H5.1@1100,1800 ; v1(1284,2388) 1284,2248 1285,2247 v1(1285,2110)
GND: C1.2 C2.2 C3.2 C4.2 C5.2 C6.2 C7.2 C8.2 C9.2 C10.2 C11.2 C12.2 C13.2 C14.2 C15.2 C17.2 C18.2 C19.2 C20.2 C21.2 C22.2 C23.2 C24.2 C25.2 C26.2 C31.2 C32.2 C34.2 D4.1 H10.1 H11.1 H12.1 H13.1 J2.1 J3.2 J5.3 J5.5 J5.9 J9.5 J11.5 R14.2 R16.2 RESET.1 RESET.3 SW1.2 SW1.4 SW2.2 SW2.4 U1.3 U1.12 U1.27 U1.39 U1.55 U2.3 U2.12 U2.27 U2.32 U2.34 U2.35 U2.39 U2.55 U4.1 U8.4 U8.9 | length 8042.8
  Top w8: v1(464,2304) 531,2304 543,2316 564,2316 ; U8.9@564,2236 564,2308 564,2316 ; U8.9@576,2208 576,2224 588,2236 588,2316 564.82,2316 564,2316 ; U8.4@634.07,2246.39 666.39,2246.39 681.72,2261.72 C18.2@708,2261.72 ; C32.2@764.82,1250.85 789.15,1250.85 800,1240 808,1240 ; C13.2@808.97,1271.67 808.97,1249.9 808,1248.93 808,1240 ; U1.55@820.44,862.2 906.24,948 907.15,948 992,1032.85 v1(992,1072) ; C20.2@890,2152.28 920.28,2152.28 929.1,2161.1 U2.12@975.59,2161.1 ; C15.2@904,2322.28 907.94,2322.28 925.56,2339.9 975.59,2339.9 U2.3@975.59,2338.27 1033.73,2338.27 1092,2280 v1(1092,2244) 1136.47,2244 1148,2232.47 1352,2232.47 1384,2200.47 U2.39@1424.41,2200.47 ; v1(970,1135) 906.76,1135 833.54,1208.22 828.22,1208.22 828,1208 826.79,1208 822.79,1212 820.89,1212 808,1224.89 808,1240 ; v1(1064,884) 1064,858.56 1048,842.56 1048,798.89 1149.72,697.17 C5.2@1149.72,692 C5.2@1149.72,690.32 ; U1.27@1123.88,1193.48 1153.25,1222.84 1153.25,1225.25 v1(1164,1236) ; v1(1152,972) 1152,945.44 U1.12@1207.4,890.04 1241.44,856 1275.68,856 1282.6,849.08 1307.38,849.08 C6.2@1307.38,843.24 ; U2.55@1229.53,2454.41 1229.53,2387.36 1244.89,2372 1266.21,2372 1274.21,2364 1296.56,2364 1308.56,2376 v1(1336,2376) ; U2.27@1249.21,2005.59 1249.21,1964 1292,1964 1304,1952 1347.64,1952 ; U2.32@1347.64,2005.59 1347.64,1952 ; U2.34@1424.41,2102.05 1480.72,2102.05 1482.67,2104 ; U2.35@1424.41,2121.73 1464.94,2121.73 1482.67,2104 ; v1(1548,2100) 1489.76,2100 ; 1347.64,1952 1347.64,1948 1415.64,2016 1496,2016 1496,2093.76 1489.76,2100 ; 1482.67,2104 1486.67,2100 1489.76,2100
  Top w10: C23.2@1196,1890.28 C2.2@1244,1890.28 C17.2@1292,1890.28
  Top w14: J9.5@165.32,1748.82 255.18,1748.82 288,1716 288,1668 ; v1(268,1632) 268,1648 284,1664 ; R14.2@269.46,2020 305.52,2020 374.5,2088.98 396.98,2088.98 v1(432,2124) 431.44,2124 C14.2@431.44,2171.61 ; R16.2@396,2334.54 433.46,2334.54 v1(464,2304) ; v1(448,1168) 404,1212 394.59,1212 470.59,1288 508,1250.59 C31.2@532.07,1250.59 ; C31.2@534.09,1250.59 C31.2@532.07,1250.59 ; v1(548,800) 614.47,800 617.92,796.54 C10.2@683.23,796.54 ; U8.9@564,2236 U8.9@576,2224 ; 564,2308 564.82,2308.82 564.82,2316 J11.5@564.82,2434.68 ; U8.4@634.07,2246.39 634.07,2274.07 v1(636,2276) ; C7.2@646.19,1185.82 646.19,1186.76 624.95,1208 568.69,1208 532.07,1244.63 C31.2@532.07,1250.59 ; C12.2@682.76,752.84 682.76,795.83 683.71,796.78 C4.2@683.71,839.77 ; D4.1@772,2235.43 772,2228.81 848,2228.81 v1(848,2224) ; C34.2@836.75,2041.82 861.59,2041.82 871.76,2052 v1(896,2052) 896,2099.72 890,2105.72 C20.2@890,2152.28 ; C1.2@853.75,2322.3 C15.2@904,2322.28 ; v1(980,2528) 989.02,2537.02 1040.12,2537.02 1040.12,2535.32 1073.14,2502.31 1140,2502.31 C24.2@1166.63,2528.94 ; C5.2@1149.72,690.32 C8.2@1149.72,644 1173.56,644 1184,633.56 v1(1184,628) ; C19.2@1255.65,2551.11 1256.54,2552 v1(1288,2552) ; C11.2@1277.72,1230 1312,1230 v1(1312,1228) ; C3.2@1278.2,1182.63 1302.04,1182.63 1312,1192.58 v1(1312,1228) ; C17.2@1292,1890.28 1350.28,1890.28 v1(1372,1912) ; C6.2@1307.38,843.24 1427.96,843.24 1442.2,829 1560,829 v1(1560,824) ; 1344.87,1300.63 1419.37,1300.63 1448,1272 1448,1236 ; v1(1548,2100) 1581.35,2133.35 C26.2@1620.61,2133.35 ; v1(1560,2344) 1560,2342.47 1562.73,2339.74 1562.73,2309.65 C25.2@1621.26,2309.65 ; v1(1616,1676) 1617.13,1677.13 1673.73,1677.13 ; v1(1620,1600) 1624.32,1604.32 1674.35,1604.32 ; v1(1660,1236) 1448,1236 ; 1674.13,1531.65 1634.54,1531.65 1634.18,1532 1624,1532 1624,1496 1662,1496 1674,1484 v1(1700,1484) 1876,1484 v1(1916,1524) ; v1(1796,2408) 1839.5,2408 1863.5,2384 v1(1932,2384) ; 284,1664 288,1668 ; 284,1664 288,1664 288,1668 ; v1(1312,1228) 1342.32,1228 1350.32,1236 1448,1236
  Bottom w8: J5.3@1897,2360 1924,2360 1932,2368 v1(1932,2384)
  Bottom w14: 576,2208 636,2268 v1(636,2276) ; v1(970,1135) 992,1113 v1(992,1072) ; v1(1164,1236) 1160,1236 1160,1264 1151,1273 1151,1354 1232,1435 ; v1(1232,1484) 1232,1435 ; v1(1312,1228) 1312,1355 1232,1435 ; v1(1796,2408) 1796,2409 1847,2409 J5.9@1847,2410 ; J5.5@1897,2260 1956,2260 1956,2096 1948,2088 v1(1908,2088)
  other v1: 404,52 1592,180 608,188 1264,272 1712,432 348,436 1400,480 1516,484 548,588 1004,836 428,848 628,944 448,972 1424,1000 1656,1056 1025,1310 300,1344 972,1492 580,1612 564,1788 796,1792 1768,1880 768,1960 48,2376 144,2396 1648,2484
ICDI_\RST\: C34.1 D2.2 J5.10 R19.2 U2.38 | length 1556
  Top w8: D2.2@745.4,2049.59 774.12,2049.59 780.47,2043.24 C34.1@801.31,2043.24 ; C34.1@801.31,2041.82 C34.1@801.31,2043.24 ; R19.2@843.63,2151.95 843.63,2100 v1(845,2100) 845,2072.22 801.31,2072.22 C34.1@801.31,2043.24 ; v1(1040,2210) 1344.55,2210 1374.55,2180 1382.09,2180 1382.88,2180.79 U2.38@1424.41,2180.79 1464.94,2180.79 1480,2165.72 v1(1480,2160) ; v1(1500,2424) 1732,2424 1768,2460 v1(1800,2460)
  Bottom w8: v1(845,2100) 957,2212 1040,2212 v1(1040,2210) ; v1(1480,2160) 1480,2282 1500,2302 v1(1500,2424) ; v1(1800,2460) J5.10@1847,2460
ICDI_TCK: J5.4 R21.2 U2.52 | length 1258.9
  Top w8: U2.52@1288.58,2454.41 1288.58,2520.58 1328,2560 1932,2560 1968,2524 1969,2524 v1(1970,2525) 1970,2502 1980,2492 1980,2334.35 1955.94,2310.28 R21.2@1952,2310.28
  Bottom w8: J5.4@1897,2310 1972,2385 1972,2500 1970,2502 v1(1970,2525)
ICDI_TDI: J5.8 U2.50 | length 731.2
  Top w8: U2.50@1327.95,2454.41 1327.95,2507.95 1348,2528 1756,2528 v1(1768,2516)
  Bottom w8: v1(1768,2516) 1769,2516 1768.99,2515.92 1768,2504 1768,2380 1788,2360 J5.8@1847,2360
ICDI_TDO: J5.6 U2.49 | length 615.4
  Top w8: U2.49@1347.64,2454.41 1347.64,2430.79 1378.43,2400 v1(1744,2400)
  Bottom w8: v1(1744,2400) 1744,2363 J5.6@1847,2260
ICDI_TMS: J5.2 R22.2 U2.51 | length 887.3
  Top w8: U2.51@1308.27,2454.41 1308.27,2519.05 1333.21,2544 1900,2544 1952,2492 v1(1950,2490) 1950,2449.72 R22.2@1952,2449.72
  Bottom w8: J5.2@1897,2410 1950,2463 v1(1950,2490)
LED_B: R11.2 | length 408.8
  Top w8: R11.2@1518.54,1450 1518.54,1494.54 1540,1516 v1(1576,1516) ; v1(1576,1716) 1617.32,1716 1617.82,1716.5 1673.73,1716.5
  Bottom w8: v1(1576,1516) v1(1576,1716)
LED_G: R12.2 | length 589
  Top w8: v1(1436,1612) 1568,1612 1599.68,1643.68 1674.35,1643.68 ; v1(1448,1356) 1518.54,1356 R12.2@1518.54,1350
  Bottom w8: v1(1436,1612) 1448,1600 v1(1448,1356)
LED_R: R2.2 | length 133.1
  Top w8: R2.2@1541.46,1572 1603.37,1572 1604.35,1571.02 1674.13,1571.02
PA0/U0RX_VCP_TXD: H6.1 U1.17 U2.18 | length 1675.6
  Top w8: v1(1070,1950) 1070.09,1950 1072.05,1948.05 U2.18@1072.05,2005.59 ; v1(1155,1720) 1427.5,1720 1500,1792.5 H6.1@1500,1800 ; U1.17@1263.08,1054.29 1292.79,1084 1400,1084 1412,1072 1436.56,1072 1464.56,1100 v1(1500,1100)
  Bottom w8: v1(1070,1950) 1152,1868 1152,1765.22 1155,1762.22 v1(1155,1720) ; v1(1500,1100) 1500,1179.44 1502,1181.44 1502,1714.31 1500,1716.31 H6.1@1500,1800
PA1/U0TX_VCP_RXD: H7.1 U1.18 U2.17 | length 1590.7
  Top w8: v1(1040,1925) 1040,1952 1052.36,1964.36 U2.17@1052.36,2005.59 ; v1(1050,1720) 1118.83,1720 1142.83,1744 1351.5,1744 1400,1792.5 H7.1@1400,1800 ; U1.18@1249.16,1068.21 1280.95,1100 v1(1424,1100)
  Bottom w8: v1(1040,1925) 1040,1868 1050,1858 v1(1050,1720) ; H7.1@1400,1800 1400,1666.31 1388,1654.31 1388,1219.5 1425,1182.5 1425,1110 v1(1424,1100)
PA2: J2.10 U1.19 | length 1286
  Top w8: U1.19@1235.24,1082.12 1269.11,1116 1336,1116 1348,1128 v1(1364,1128) ; v1(1364,544) 1856,544 J2.10@1900,500
  Bottom w8: v1(1364,544) v1(1364,1128)
PA3: J2.9 U1.20 | length 1237.1
  Top w8: U1.20@1221.32,1096.04 1257.27,1132 1312,1132 1340,1160 v1(1396,1160) ; v1(1396,648) 1852,648 J2.9@1900,600
  Bottom w8: v1(1396,648) v1(1396,1160)
PA4: J2.8 U1.21 | length 1198.5
  Top w8: U1.21@1207.4,1109.96 1245.94,1148.5 1307.29,1148.5 1342.79,1184 v1(1476,1184) ; v1(1476,732) 1625,732 1637,744 1856,744 J2.8@1900,700
  Bottom w8: v1(1476,732) v1(1476,1184)
PA5: J1.8 U1.22 | length 1724.8
  Top w8: J1.8@100,700 152,648 226.08,648 286.08,588 385,588 457,516 1038.86,516 1046.86,508 v1(1084,508) ; v1(1092,1004) 1104,1016 1104,1034.4 U1.22@1193.48,1123.88
  Bottom w8: v1(1084,508) 1084,758 1092,766 v1(1092,1004)
PA6: J1.9 U1.23 | length 1701.2
  Top w8: J1.9@100,600 156,544 376,544 440,480 757,480 772,465 v1(980,465) ; v1(976,908) 994.78,926.78 1005.89,926.78 1044,964.89 1044,1002.24 U1.23@1179.56,1137.8
  Bottom w8: v1(976,908) 976,688.5 980,684.5 v1(980,465)
PA7: J1.10 U1.24 | length 1809.7
  Top w8: J1.10@100,500 250,350 v1(950,350) ; v1(1000,952) 1000,980.17 1132,1112.17 1132,1118.08 U1.24@1165.64,1151.72
  Bottom w8: v1(950,350) 950,913.11 970.11,933.22 981.22,933.22 v1(1000,952)
PB0: J1.3 R25.1 U1.45 | length 1318.8
  Top w8: v1(36,1580) R25.1@226.54,1580 ; J1.3@100,1200 141.51,1200 185.51,1156 401.05,1156 416.27,1140.78 599.55,1140.78 615.32,1125 740.65,1125 744.91,1120.74 753.98,1120.74 U1.45@778.68,1096.04
  Bottom w8: v1(36,1580) 36,1268 48,1256 48,1252 J1.3@100,1200
PB1: J1.4 R29.2 U1.46 | length 1224
  Top w8: J1.4@100,1100 141.51,1100 182.51,1141 251,1141 272,1120 388,1120 396,1112 602,1112 604,1110 734.19,1110 763.41,1080.78 U1.46@764.76,1082.12 ; v1(152,1516) R29.2@226.54,1516
  Bottom w8: J1.4@100,1100 131.19,1131.19 139.19,1131.19 152,1144 v1(152,1516)
PB2: J2.2 U1.47 | length 2900.4
  Top w8: v1(356,1096) 536,1096 540,1092 727.05,1092 U1.47@750.84,1068.21 ; v1(404,1612) 452,1612 452,1613.11 514.89,1676 604,1676 608,1672 1477,1672 v1(1480,1675) ; v1(1476,1280) 1716,1280 1744,1252 1810.49,1252 1858.49,1300 J2.2@1900,1300
  Bottom w8: v1(356,1096) 356,1460 404,1508 v1(404,1612) ; v1(1476,1280) 1476,1328 1480,1332 v1(1480,1675)
PB3: J4.3 U1.48 | length 2559.4
  Top w8: v1(384,1072) 686.99,1072 688,1070.99 720.22,1070.99 U1.48@736.92,1054.29 ; v1(428,1580) 816,1580 940,1456 v1(1364,1456) ; v1(1365,1210) 1610,1210 1620,1200 J4.3@1800,1200
  Bottom w8: v1(384,1072) 384,1456 428,1500 v1(428,1580) ; v1(1364,1456) 1364,1332 1365,1331 v1(1365,1210)
PB4: J1.7 U1.58 | length 843.6
  Top w8: J1.7@100,800 152,748 418.59,748 454.59,712 753.76,712 U1.58@862.2,820.44
PB5: J1.2 U1.57 | length 1312.1
  Top w8: J1.2@100,1300 146,1254 146,1250 v1(330,1250) ; v1(330,775) 420,775 467,728 741.92,728 U1.57@848.28,834.36
  Bottom w8: v1(330,775) 329,775 328,776 328,1170.06 330,1172.06 v1(330,1250)
PB6: J2.7 R9.2 U1.1 | length 1406.4
  Top w8: R9.2@847.2,633.34 847.2,631.37 882.57,596 1076,596 ; U1.1@1054.29,736.92 1070.99,720.22 1070.99,657.01 1076,652 1076,596 ; v1(1420,596) 1076,596 ; v1(1420,764) 1760,764 1765,759 1817.49,759 1858.49,800 J2.7@1900,800
  Bottom w8: v1(1420,596) v1(1420,764)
